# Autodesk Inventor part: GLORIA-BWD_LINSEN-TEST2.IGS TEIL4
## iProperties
Created: 2005-04
Part Number: GLORIA-BWD_LINSEN-TEST2.IGS TEIL4
Document SubType Name: Modeling
Designer: Nordmeyer
Manufacturer: Standard
Standards Organization: Custom
Author: Nordmeyer
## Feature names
1. Erst1
